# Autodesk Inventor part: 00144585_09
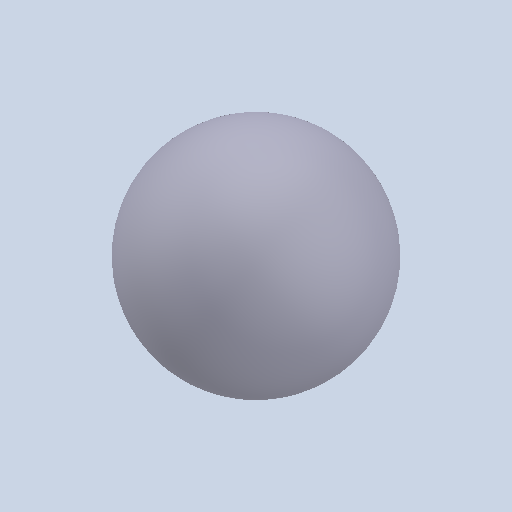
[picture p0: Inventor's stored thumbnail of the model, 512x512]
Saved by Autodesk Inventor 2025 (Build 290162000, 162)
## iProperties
Created: 2021-02
Part Number: 00144585_09
Material: Generico
Document SubType Name: Modeling
Designer: Ryzen5700u
Density: 1 g/cm^3
Appearance: Default
Author: Ryzen5700u
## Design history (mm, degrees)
feature "Solido1"
node "Solido2"
